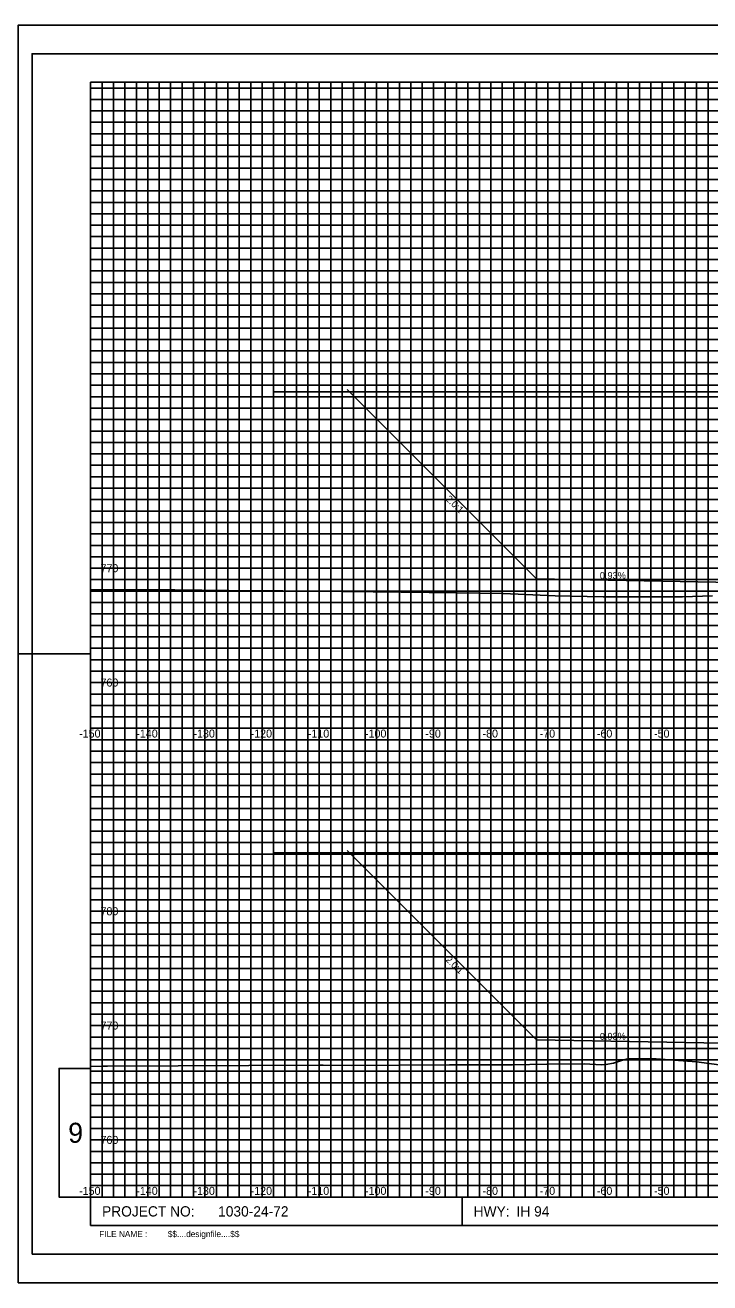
# Model space of a CAD drawing. Extents: x 578243 to 601557, y 174899 to 175559.
# Drawn here: x 600198.4 to 600318.2, y 175338.8 to 175558.8 of the extents above; entities that cross this region are included whole.
import ezdxf

# ---------------------------------------------------------------- set-up
doc = ezdxf.new("R2010")
doc.units = 0
for name, color, linetype in [('E_PROF_Grid', 7, 'Continuous'), ('E_PROF_GridMin', 7, 'Continuous'), ('P_CRDR_Label', 7, 'Continuous'), ('P_CRDR_Link', 7, 'Continuous'), ('P_E_XS_Ground', 7, 'Continuous'), ('P_RW_SlopeIntercepts', 7, 'Continuous'), ('P_XS_Text', 7, 'Continuous'), ('PLT_Sheet_Border', 7, 'Continuous'), ('PLT_Sheet_Info', 7, 'Continuous')]:
    doc.layers.add(name, color=color, linetype=linetype)

msp = doc.modelspace()

# ---------------------------------------------------------------- linework, layer by layer
at = {"layer": 'E_PROF_Grid'}
for p, q in [((600219.84, 175353.8), (600219.84, 175548.8)), ((600229.84, 175353.8), (600229.84, 175548.8)), ((600239.84, 175353.8), (600239.84, 175548.8)), ((600249.84, 175353.8), (600249.84, 175548.8)), ((600259.84, 175353.8), (600259.84, 175548.8)), ((600269.84, 175353.8), (600269.84, 175548.8)), ((600279.84, 175353.8), (600279.84, 175548.8)), ((600289.84, 175353.8), (600289.84, 175548.8)), ((600299.84, 175353.8), (600299.84, 175548.8)), ((600309.84, 175353.8), (600309.84, 175548.8)), ((600209.84, 175543.8), (600524.84, 175543.8)), ((600209.84, 175533.8), (600524.84, 175533.8)), ((600209.84, 175523.8), (600524.84, 175523.8)), ((600209.84, 175513.8), (600524.84, 175513.8)), ((600209.84, 175503.8), (600524.84, 175503.8)), ((600209.84, 175493.8), (600524.84, 175493.8)), ((600209.84, 175483.8), (600524.84, 175483.8)), ((600209.84, 175473.8), (600524.84, 175473.8)), ((600209.84, 175463.8), (600524.84, 175463.8)), ((600209.84, 175453.8), (600524.84, 175453.8)), ((600209.84, 175443.8), (600524.84, 175443.8)), ((600209.84, 175433.8), (600524.84, 175433.8)), ((600209.84, 175423.8), (600524.84, 175423.8)), ((600209.84, 175413.8), (600524.84, 175413.8)), ((600209.84, 175403.8), (600524.84, 175403.8)), ((600209.84, 175393.8), (600524.84, 175393.8)), ((600209.84, 175383.8), (600524.84, 175383.8)), ((600209.84, 175373.8), (600524.84, 175373.8)), ((600209.84, 175363.8), (600524.84, 175363.8))]:
    msp.add_line(p, q, dxfattribs=at)
at = {"layer": 'E_PROF_GridMin'}
for p, q in [((600209.84, 175547.8), (600524.84, 175547.8)), ((600211.84, 175353.8), (600211.84, 175548.8)), ((600213.84, 175353.8), (600213.84, 175548.8)), ((600215.84, 175353.8), (600215.84, 175548.8)), ((600217.84, 175353.8), (600217.84, 175548.8)), ((600221.84, 175353.8), (600221.84, 175548.8)), ((600223.84, 175353.8), (600223.84, 175548.8)), ((600225.84, 175353.8), (600225.84, 175548.8)), ((600227.84, 175353.8), (600227.84, 175548.8)), ((600231.84, 175353.8), (600231.84, 175548.8)), ((600233.84, 175353.8), (600233.84, 175548.8)), ((600235.84, 175353.8), (600235.84, 175548.8)), ((600237.84, 175353.8), (600237.84, 175548.8)), ((600241.84, 175353.8), (600241.84, 175548.8)), ((600243.84, 175353.8), (600243.84, 175548.8)), ((600245.84, 175353.8), (600245.84, 175548.8)), ((600247.84, 175353.8), (600247.84, 175548.8)), ((600251.84, 175353.8), (600251.84, 175548.8)), ((600253.84, 175353.8), (600253.84, 175548.8)), ((600255.84, 175353.8), (600255.84, 175548.8)), ((600257.84, 175353.8), (600257.84, 175548.8)), ((600261.84, 175353.8), (600261.84, 175548.8)), ((600263.84, 175353.8), (600263.84, 175548.8)), ((600265.84, 175353.8), (600265.84, 175548.8)), ((600267.84, 175353.8), (600267.84, 175548.8)), ((600271.84, 175353.8), (600271.84, 175548.8)), ((600273.84, 175353.8), (600273.84, 175548.8)), ((600275.84, 175353.8), (600275.84, 175548.8)), ((600277.84, 175353.8), (600277.84, 175548.8)), ((600281.84, 175353.8), (600281.84, 175548.8)), ((600283.84, 175353.8), (600283.84, 175548.8)), ((600285.84, 175353.8), (600285.84, 175548.8)), ((600287.84, 175353.8), (600287.84, 175548.8)), ((600291.84, 175353.8), (600291.84, 175548.8)), ((600293.84, 175353.8), (600293.84, 175548.8)), ((600295.84, 175353.8), (600295.84, 175548.8)), ((600297.84, 175353.8), (600297.84, 175548.8)), ((600301.84, 175353.8), (600301.84, 175548.8)), ((600303.84, 175353.8), (600303.84, 175548.8)), ((600305.84, 175353.8), (600305.84, 175548.8)), ((600307.84, 175353.8), (600307.84, 175548.8)), ((600311.84, 175353.8), (600311.84, 175548.8)), ((600313.84, 175353.8), (600313.84, 175548.8)), ((600315.84, 175353.8), (600315.84, 175548.8)), ((600317.84, 175353.8), (600317.84, 175548.8)), ((600209.84, 175545.8), (600524.84, 175545.8)), ((600209.84, 175541.8), (600524.84, 175541.8)), ((600209.84, 175539.8), (600524.84, 175539.8)), ((600209.84, 175537.8), (600524.84, 175537.8)), ((600209.84, 175535.8), (600524.84, 175535.8)), ((600209.84, 175531.8), (600524.84, 175531.8)), ((600209.84, 175529.8), (600524.84, 175529.8)), ((600209.84, 175527.8), (600524.84, 175527.8)), ((600209.84, 175525.8), (600524.84, 175525.8)), ((600209.84, 175521.8), (600524.84, 175521.8)), ((600209.84, 175519.8), (600524.84, 175519.8)), ((600209.84, 175517.8), (600524.84, 175517.8)), ((600209.84, 175515.8), (600524.84, 175515.8)), ((600209.84, 175511.8), (600524.84, 175511.8)), ((600209.84, 175509.8), (600524.84, 175509.8)), ((600209.84, 175507.8), (600524.84, 175507.8)), ((600209.84, 175505.8), (600524.84, 175505.8)), ((600209.84, 175501.8), (600524.84, 175501.8)), ((600209.84, 175499.8), (600524.84, 175499.8)), ((600209.84, 175497.8), (600524.84, 175497.8)), ((600209.84, 175495.8), (600524.84, 175495.8)), ((600209.84, 175491.8), (600524.84, 175491.8)), ((600209.84, 175489.8), (600524.84, 175489.8)), ((600209.84, 175487.8), (600524.84, 175487.8)), ((600209.84, 175485.8), (600524.84, 175485.8)), ((600209.84, 175481.8), (600524.84, 175481.8)), ((600209.84, 175479.8), (600524.84, 175479.8)), ((600209.84, 175477.8), (600524.84, 175477.8)), ((600209.84, 175475.8), (600524.84, 175475.8)), ((600209.84, 175471.8), (600524.84, 175471.8)), ((600209.84, 175469.8), (600524.84, 175469.8)), ((600209.84, 175467.8), (600524.84, 175467.8)), ((600209.84, 175465.8), (600524.84, 175465.8)), ((600209.84, 175461.8), (600524.84, 175461.8)), ((600209.84, 175459.8), (600524.84, 175459.8)), ((600209.84, 175457.8), (600524.84, 175457.8)), ((600209.84, 175455.8), (600524.84, 175455.8)), ((600209.84, 175451.8), (600524.84, 175451.8)), ((600209.84, 175449.8), (600524.84, 175449.8)), ((600209.84, 175447.8), (600524.84, 175447.8)), ((600209.84, 175445.8), (600524.84, 175445.8)), ((600209.84, 175441.8), (600524.84, 175441.8)), ((600209.84, 175439.8), (600524.84, 175439.8)), ((600209.84, 175437.8), (600524.84, 175437.8)), ((600209.84, 175435.8), (600524.84, 175435.8)), ((600209.84, 175431.8), (600524.84, 175431.8)), ((600209.84, 175429.8), (600524.84, 175429.8)), ((600209.84, 175427.8), (600524.84, 175427.8)), ((600209.84, 175425.8), (600524.84, 175425.8)), ((600209.84, 175421.8), (600524.84, 175421.8)), ((600209.84, 175419.8), (600524.84, 175419.8)), ((600209.84, 175417.8), (600524.84, 175417.8)), ((600209.84, 175415.8), (600524.84, 175415.8)), ((600209.84, 175411.8), (600524.84, 175411.8)), ((600209.84, 175409.8), (600524.84, 175409.8)), ((600209.84, 175407.8), (600524.84, 175407.8)), ((600209.84, 175405.8), (600524.84, 175405.8)), ((600209.84, 175401.8), (600524.84, 175401.8)), ((600209.84, 175399.8), (600524.84, 175399.8)), ((600209.84, 175397.8), (600524.84, 175397.8)), ((600209.84, 175395.8), (600524.84, 175395.8)), ((600209.84, 175391.8), (600524.84, 175391.8)), ((600209.84, 175389.8), (600524.84, 175389.8)), ((600209.84, 175387.8), (600524.84, 175387.8)), ((600209.84, 175385.8), (600524.84, 175385.8)), ((600209.84, 175381.8), (600524.84, 175381.8)), ((600209.84, 175379.8), (600524.84, 175379.8)), ((600209.84, 175377.8), (600524.84, 175377.8)), ((600209.84, 175375.8), (600524.84, 175375.8)), ((600209.84, 175371.8), (600524.84, 175371.8)), ((600209.84, 175369.8), (600524.84, 175369.8)), ((600209.84, 175367.8), (600524.84, 175367.8)), ((600209.84, 175365.8), (600524.84, 175365.8)), ((600209.84, 175361.8), (600524.84, 175361.8)), ((600209.84, 175359.8), (600524.84, 175359.8)), ((600209.84, 175357.8), (600524.84, 175357.8)), ((600209.84, 175355.8), (600524.84, 175355.8))]:
    msp.add_line(p, q, dxfattribs=at)
at = {"layer": 'P_CRDR_Link'}
for p, q in [((600254.72, 175495.04), (600287.84, 175461.93)), ((600254.72, 175414.44), (600287.84, 175381.32))]:
    msp.add_line(p, q, dxfattribs=at)
for points in [[(600322.34, 175461.29), (600287.84, 175461.93)], [(600320.34, 175380.72), (600287.84, 175381.32)], [(600320.34, 175380.72), (600287.84, 175381.32)]]:
    msp.add_lwpolyline(points, dxfattribs=at)
at = {"layer": 'P_E_XS_Ground'}
for points in [[(600209.84, 175460.1), (600221.49, 175460.04), (600224.57, 175460.02), (600238.72, 175459.87), (600243.46, 175459.82), (600259.26, 175459.65), (600273.96, 175459.47), (600281.99, 175459.38), (600291.08, 175458.98), (600299.47, 175458.82), (600313.38, 175458.77), (600318.6, 175459)], [(600209.84, 175376.64), (600211.78, 175376.68), (600212.35, 175376.69), (600212.79, 175376.7), (600249.9, 175376.87), (600250.28, 175376.87), (600250.53, 175376.87), (600255.41, 175376.84), (600272.59, 175376.96), (600283.65, 175376.95), (600289.66, 175377.03), (600296.14, 175377.11), (600299.22, 175376.96), (600299.98, 175376.99), (600301.31, 175377.24), (600303.03, 175377.83), (600303.75, 175377.99), (600308.04, 175377.98), (600308.75, 175377.96), (600315.83, 175377.47), (600322.39, 175376.57)]]:
    msp.add_lwpolyline(points, dxfattribs=at)
at = {"layer": 'P_RW_SlopeIntercepts'}
for p, q in [((600241.84, 175494.63), (600501.84, 175494.63)), ((600241.84, 175414.02), (600501.84, 175414.02))]:
    msp.add_line(p, q, dxfattribs=at)
at = {"layer": 'PLT_Sheet_Border'}
for points in [[(600197.19, 175338.8), (600537.19, 175338.8), (600537.19, 175558.8), (600197.19, 175558.8)], [(600199.59, 175343.8), (600530.59, 175343.8), (600530.59, 175553.8), (600199.59, 175553.8)]]:
    msp.add_lwpolyline(points, close=True, dxfattribs=at)
at = {"layer": 'PLT_Sheet_Info'}
for p, q in [((600197.19, 175558.8), (600207.19, 175558.8)), ((600209.84, 175548.8), (600524.84, 175548.8)), ((600209.84, 175348.8), (600209.84, 175548.8)), ((600197.19, 175448.8), (600209.84, 175448.8)), ((600209.84, 175353.8), (600524.84, 175353.8)), ((600274.84, 175348.8), (600274.84, 175353.8)), ((600209.84, 175348.8), (600524.84, 175348.8)), ((600197.19, 175338.8), (600207.19, 175338.8))]:
    msp.add_line(p, q, dxfattribs=at)
msp.add_lwpolyline([(600209.84, 175376.3), (600204.34, 175376.3), (600204.34, 175353.8), (600209.84, 175353.8)], close=True, dxfattribs=at)

# ---------------------------------------------------------------- texts
at = {"layer": 'P_CRDR_Label'}
for s, rotation, p in [('2.0:1', 315.8532, (600271.83, 175475.82)), ('0.93%', 0.4313, (600298.91, 175461.92)), ('2.0:1', 315.8532, (600271.83, 175395.21)), ('0.93%', 0.4313, (600298.91, 175381.31))]:
    msp.add_text(s, height=1.2, rotation=rotation, dxfattribs=at).set_placement(p)
at = {"layer": 'P_XS_Text'}
for s, p in [('770', (600211.57, 175463.1)), ('760', (600211.57, 175443.1)), ('-150', (600207.83, 175434.18)), ('-140', (600217.83, 175434.18)), ('-130', (600227.83, 175434.18)), ('-120', (600237.83, 175434.18)), ('-110', (600247.83, 175434.18)), ('-100', (600257.83, 175434.18)), ('-90', (600268.39, 175434.18)), ('-80', (600278.39, 175434.18)), ('-70', (600288.39, 175434.18)), ('-60', (600298.39, 175434.18)), ('-50', (600308.39, 175434.18)), ('780', (600211.57, 175403.1)), ('770', (600211.57, 175383.1)), ('760', (600211.57, 175363.1)), ('-150', (600207.83, 175354.19)), ('-140', (600217.83, 175354.19)), ('-130', (600227.83, 175354.19)), ('-120', (600237.83, 175354.19)), ('-110', (600247.83, 175354.19)), ('-100', (600257.83, 175354.19)), ('-90', (600268.39, 175354.19)), ('-80', (600278.39, 175354.19)), ('-70', (600288.39, 175354.19)), ('-60', (600298.39, 175354.19)), ('-50', (600308.39, 175354.19))]:
    msp.add_text(s, height=1.4, rotation=360, dxfattribs=at).set_placement(p)
at = {"layer": 'PLT_Sheet_Info'}
for s, height, p in [('9', 3.5, (600205.92, 175363.3)), ('PROJECT NO:', 1.8, (600211.84, 175350.4)), ('1030-24-72             ', 1.8, (600232.14, 175350.4)), ('HWY:', 1.8, (600276.84, 175350.4)), ('IH 94               ', 1.8, (600284.34, 175350.4)), ('FILE NAME :', 1.08, (600211.34, 175346.8))]:
    msp.add_text(s, height=height, dxfattribs=at).set_placement(p)
msp.add_text('$$....designfile....$$', height=1.08, rotation=360, dxfattribs=at).set_placement((600223.34, 175346.8))

doc.saveas('drawing.dxf')
